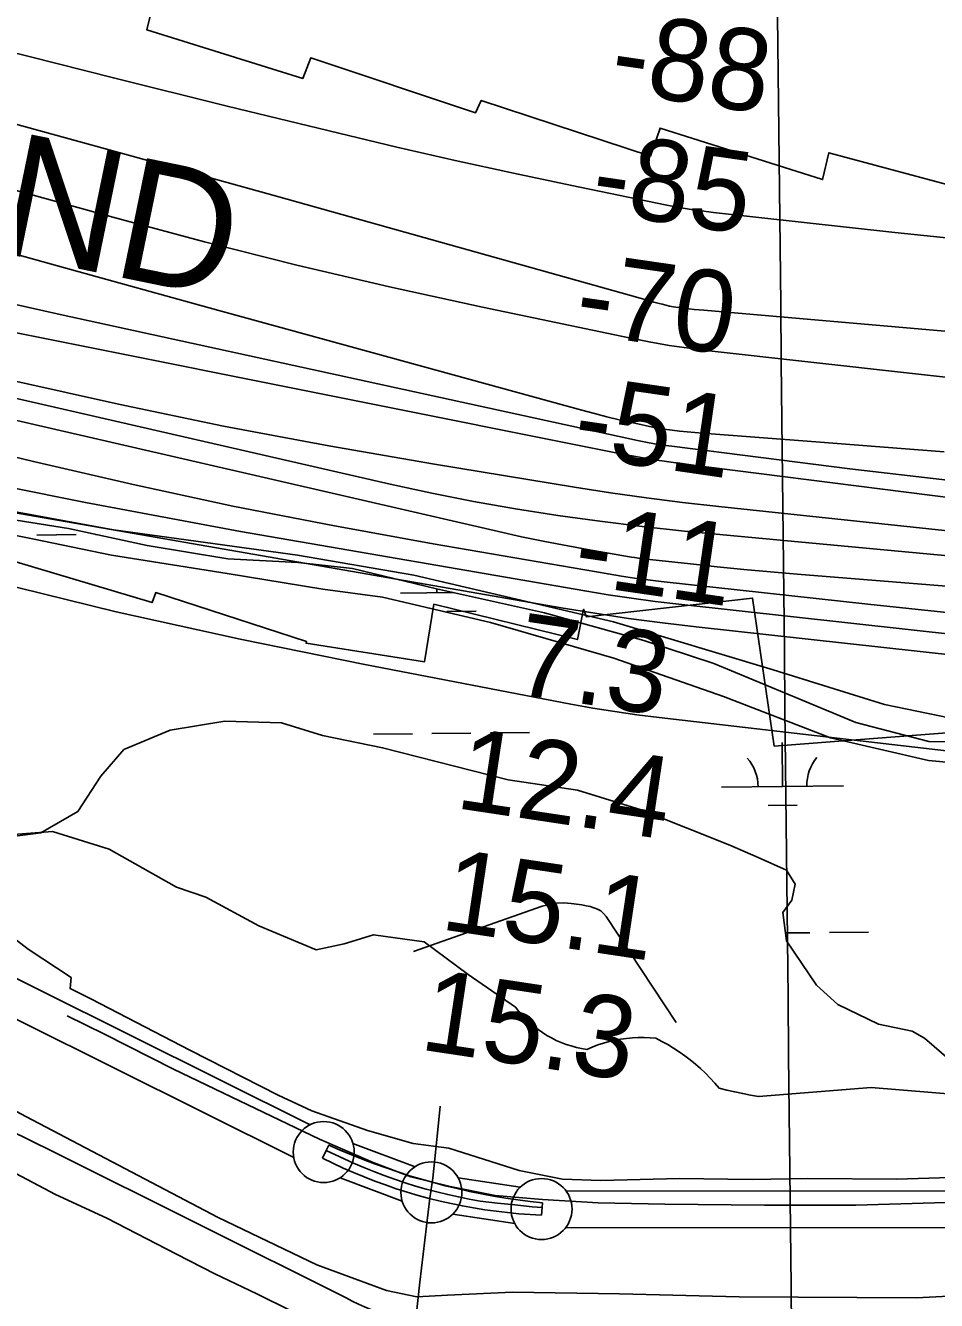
# Model space of a CAD drawing. Extents: x 3651524 to 3689615, y 505651 to 531377.
# Drawn here: x 3665685 to 3666432, y 512395 to 513440 of the extents above; entities that cross this region are included whole.
import ezdxf

# ---------------------------------------------------------------- set-up
doc = ezdxf.new("R2010")
doc.units = 0
for name, color, linetype in [('V-BRDG-OTLN', 7, 'Continuous'), ('V-FLOD-BASE', 7, 'Continuous'), ('V-GRID-MAJR', 7, 'Continuous'), ('V-LEVE-TOET', 7, 'Continuous'), ('V-RIVR-EDGE', 7, 'Continuous'), ('V-RIVR-RANG', 7, 'Continuous'), ('V-ROAD-CNTR', 7, 'Continuous'), ('V-RRAP-RVMT', 7, 'Continuous'), ('V-RRAP-RVMT-IDEN', 7, 'Continuous'), ('V-SITE-VEGE', 7, 'Continuous'), ('V-SURV-LINE', 7, 'Continuous'), ('V-TOPO-DPTH', 7, 'Continuous'), ('V-TOPO-MAJR', 7, 'Continuous'), ('V-TOPO-MINR', 7, 'Continuous'), ('V-TOPO-SHOR', 7, 'Continuous'), ('V-TOPO-WATR', 7, 'Continuous'), ('V-UTIL-LINE', 7, 'Continuous'), ('V-WETL-SWMP', 7, 'Continuous')]:
    doc.layers.add(name, color=color, linetype=linetype)

msp = doc.modelspace()

# ---------------------------------------------------------------- linework, layer by layer
at = {"layer": 'V-BRDG-OTLN'}
msp.add_lwpolyline([(3665928.931, 512511.559), (3665931.945, 512517.758), (3665934.19, 512522.374), (3665943.404, 512518.278), (3665952.698, 512514.344), (3665962.071, 512510.578), (3665971.521, 512506.977), (3665981.038, 512503.547), (3665990.623, 512500.286), (3666000.267, 512497.198), (3666009.964, 512494.286), (3666019.719, 512491.546), (3666029.518, 512488.984), (3666039.361, 512486.6), (3666049.24, 512484.394), (3666059.153, 512482.366), (3666069.096, 512480.519), (3666079.061, 512478.856), (3666089.047, 512477.375), (3666099.05, 512476.079), (3666109.06, 512474.963), (3666108.792, 512471.131), (3666108.354, 512464.924), (3666099.048, 512465.409), (3666089.748, 512466.093), (3666080.458, 512466.974), (3666071.185, 512468.057), (3666061.936, 512469.335), (3666052.714, 512470.81), (3666043.52, 512472.483), (3666034.362, 512474.346), (3666025.244, 512476.411), (3666016.171, 512478.668), (3666007.148, 512481.115), (3665998.18, 512483.755), (3665989.271, 512486.581), (3665980.424, 512489.6), (3665971.644, 512492.801), (3665962.94, 512496.19), (3665954.31, 512499.762), (3665945.763, 512503.514), (3665937.301, 512507.45)], close=True, dxfattribs=at)
msp.add_lwpolyline([(3665931.954, 512517.754), (3665954.408, 512507.614), (3665962.688, 512504.018), (3665971.052, 512500.596), (3665979.49, 512497.354), (3665988.001, 512494.292), (3665996.58, 512491.412), (3666005.221, 512488.715), (3666013.919, 512486.206), (3666022.67, 512483.884), (3666031.468, 512481.748), (3666040.305, 512479.802), (3666049.183, 512478.047), (3666058.092, 512476.483), (3666072.317, 512474.789), (3666086.555, 512473.238), (3666100.797, 512471.836), (3666108.79, 512471.131), (3666108.8, 512471.131)], dxfattribs=at)
at = {"layer": 'V-FLOD-BASE'}
msp.add_lwpolyline([(3665719.484, 512628.143), (3665750.173, 512613.311), (3665806.868, 512584.408), (3665860.874, 512558.609), (3665926.487, 512527.076), (3665970.442, 512507.909), (3666001.225, 512496.254), (3666033.549, 512488.39), (3666070.325, 512480.99), (3666109.083, 512477.611), (3666154.743, 512474.93), (3666209.525, 512473.851), (3666291.246, 512473.122), (3666366.064, 512473.028), (3666467.362, 512476.175)], dxfattribs=at)
at = {"layer": 'V-GRID-MAJR'}
msp.add_spline([(3666325.988, 511176.12), (3666261.669, 517233.653), (3666197.317, 523294.271), (3666167.785, 526075.609)], degree=3, dxfattribs=at)
at = {"layer": 'V-LEVE-TOET'}
for points in [[(3664386.871, 513072.496), (3664533.157, 513026.422), (3664686.155, 512973.7), (3664856.979, 512918.834), (3665006.421, 512864.314), (3665127.78, 512816.344), (3665265.743, 512759.809), (3665352.875, 512716.488), (3665511.962, 512638.232), (3665685.632, 512545.793), (3665843.402, 512463.078), (3665924.19, 512424.269), (3665981.294, 512403.16)], [(3665655, 512707.747), (3665687.625, 512682.962), (3665722.918, 512659.525), (3665721.943, 512650.585), (3665738.905, 512642.205), (3665820.602, 512599.836), (3665892.472, 512563.209), (3665920.143, 512550.426), (3665965.643, 512534.162), (3666003.101, 512523.65), (3666032.512, 512519.779), (3666090.047, 512501.345), (3666125.707, 512494.388), (3666156.885, 512493.198), (3666221.453, 512494.837), (3666281.129, 512494.226), (3666326.552, 512494.886), (3666399.59, 512494.337), (3666452.131, 512495.92)], [(3666031.187, 512399.388), (3666084.618, 512401.864), (3666172.356, 512400.496), (3666270.34, 512397.837), (3666415.523, 512397.184), (3666543.751, 512403.576), (3666666.147, 512418.846), (3666821.365, 512443.266), (3667033.2, 512474.279), (3667149.361, 512489.965), (3667298.004, 512510.703), (3667461.341, 512532.846), (3667565.5, 512543.133), (3667683.467, 512553.483), (3667780.077, 512559.281), (3667909.216, 512561.225), (3668049.549, 512569.097), (3668206.739, 512572.063), (3668323.846, 512575.731), (3668386.645, 512574.244)], [(3665981.294, 512403.16), (3666006.31, 512397.831), (3666031.187, 512399.388)]]:
    msp.add_lwpolyline(points, dxfattribs=at)
at = {"layer": 'V-RIVR-EDGE'}
for points in [[(3665653.21, 513045.458), (3665757.62, 513026.589), (3665908.251, 513005.806), (3666003.662, 512989.361), (3666167.457, 512951.135)], [(3666167.457, 512951.135), (3666298.231, 512911.791), (3666389.41, 512883.35), (3666495.614, 512861.476)]]:
    msp.add_lwpolyline(points, dxfattribs=at)
at = {"layer": 'V-ROAD-CNTR'}
msp.add_lwpolyline([(3665948.388, 512397.067), (3665707.347, 512517.244), (3665299.022, 512718.05), (3665160.48, 512783.825)], dxfattribs=at)
msp.add_arc((3666010.459, 512503.109), 122.873, 239.657964, 280.958256, dxfattribs=at)
at = {"layer": 'V-RRAP-RVMT'}
for points in [[(3665552.051, 513515.327), (3665787.533, 513447.498), (3665784.783, 513436.238), (3665912.777, 513396.32), (3665919.29, 513413.291), (3666054.22, 513368.153), (3666059.008, 513378.347), (3666197.78, 513332.763), (3666205.502, 513355.639), (3666338.703, 513313.466), (3666343.765, 513335.427), (3666494.756, 513294.918), (3666467.097, 513184.942)], [(3666444.06, 512860.437), (3666299.16, 512849.288), (3666281.401, 512970.49), (3666145.148, 512955.265), (3666142.901, 512961.337), (3666137.757, 512936.548), (3666020.107, 512965.537), (3666012.396, 512918.245), (3665915.454, 512933.466), (3665915.731, 512935.025), (3665792.246, 512975.019), (3665789.176, 512966.909), (3665658.82, 513005.756)]]:
    msp.add_lwpolyline(points, dxfattribs=at)
at = {"layer": 'V-SITE-VEGE'}
for points in [[(3665638.08, 513029.705), (3665691.092, 513019.182), (3665755.836, 513005.753), (3665850.705, 512990.694), (3665929.174, 512977.774), (3665977.933, 512971.357), (3666066.63, 512950.511), (3666167.768, 512921.304), (3666257.401, 512889.83), (3666345.273, 512856.133), (3666425.54, 512837.461), (3666520.383, 512828.603)], [(3666182.807, 512610.209), (3666177.988, 512609.766), (3666173.194, 512609.109), (3666168.434, 512608.234), (3666163.722, 512607.149), (3666159.06, 512605.851), (3666154.465, 512604.343), (3666149.941, 512602.631), (3666145.499, 512600.716), (3666141.198, 512601.437), (3666136.94, 512602.369), (3666132.729, 512603.506), (3666128.582, 512604.847), (3666124.504, 512606.391), (3666120.509, 512608.132), (3666116.605, 512610.067), (3666112.798, 512612.193), (3666109.101, 512614.501), (3666105.522, 512616.988), (3666102.069, 512619.646), (3666098.751, 512622.47), (3666095.576, 512625.454), (3666092.552, 512628.59), (3666089.684, 512631.868), (3666086.981, 512635.284), (3666048.317, 512662.126), (3666012.307, 512688.979), (3665970.64, 512694.541), (3665946.752, 512687.343), (3665923.739, 512682.362), (3665876.69, 512702.076), (3665833.168, 512725.349), (3665809.209, 512733.654), (3665754.13, 512764.847), (3665707.548, 512779.247), (3665672.124, 512776.422)], [(3666507.739, 512558.851), (3666378.665, 512569.39), (3666286.196, 512562.111), (3666279.737, 512563.254), (3666273.271, 512564.506), (3666266.814, 512565.865), (3666260.371, 512567.332), (3666253.959, 512568.901), (3666250.368, 512573.128), (3666246.631, 512577.222), (3666242.746, 512581.176), (3666238.717, 512584.992), (3666234.56, 512588.658), (3666230.269, 512592.168), (3666225.856, 512595.525), (3666221.322, 512598.719), (3666216.677, 512601.748), (3666211.925, 512604.603), (3666207.074, 512607.29), (3666202.128, 512609.797), (3666197.311, 512610.227), (3666192.478, 512610.438), (3666187.638, 512610.434), (3666182.807, 512610.209)]]:
    msp.add_lwpolyline(points, dxfattribs=at)
at = {"layer": 'V-SURV-LINE'}
for points in [[(3665548.874, 512723.09), (3665918.674, 512538.911)], [(3665905.284, 512512.066), (3665535.485, 512696.244)], [(3665953.834, 512523.622), (3666004.709, 512504.572)], [(3665994.183, 512476.479), (3665943.308, 512495.529)], [(3666040.143, 512495.366), (3666090.859, 512487.696)], [(3666128.364, 512484.861), (3666481.904, 512484.605)], [(3666086.389, 512458.031), (3666035.673, 512465.701)], [(3666481.881, 512454.605), (3666128.342, 512454.861)]]:
    msp.add_lwpolyline(points, dxfattribs=at)
for centre in [(3665929.866, 512516.58), (3666018.151, 512483.522), (3666108.381, 512469.875)]:
    msp.add_circle(centre, 25, dxfattribs=at)
at = {"layer": 'V-TOPO-DPTH'}
for points in [[(3667391.536, 512903.862), (3666317.776, 512990.235), (3666295.963, 512992.087), (3666274.163, 512994.068), (3666252.381, 512996.242), (3666230.611, 512998.545), (3666192.049, 513002.797), (3666189.573, 513003.093), (3666184.634, 513003.787), (3666182.172, 513004.185), (3666148.982, 513009.855), (3666129.96, 513013.273), (3666110.982, 513016.908), (3666092.069, 513020.867), (3666073.199, 513025.044), (3665189.502, 513228.594)], [(3667391.536, 512903.862), (3666317.776, 512990.235), (3666295.963, 512992.087), (3666274.163, 512994.068), (3666252.381, 512996.242), (3666230.611, 512998.545), (3666192.049, 513002.797), (3666189.573, 513003.093), (3666184.634, 513003.787), (3666182.172, 513004.185), (3666148.982, 513009.855), (3666129.96, 513013.273), (3666110.982, 513016.908), (3666092.069, 513020.867), (3666073.199, 513025.044), (3665189.502, 513228.594)], [(3665481.498, 513227.334), (3666172.066, 513089.108), (3666185.551, 513086.559), (3666199.068, 513084.204), (3666212.632, 513082.14), (3666226.228, 513080.27), (3666528.081, 513042.05), (3666673.055, 513025.131), (3666818.207, 513010.104), (3666963.624, 512997.914), (3667109.218, 512987.615), (3667364.484, 512972.063), (3667382.584, 512971.144), (3667400.69, 512970.47), (3667418.806, 512970.164), (3667436.928, 512970.102), (3668037.032, 513010.232)], [(3668037.032, 513010.232), (3667436.928, 512970.102), (3667418.806, 512970.164), (3667400.69, 512970.47), (3667382.584, 512971.144), (3667364.484, 512972.063), (3667109.218, 512987.615), (3666963.624, 512997.914), (3666818.207, 513010.104), (3666673.055, 513025.131), (3666528.081, 513042.05), (3666226.228, 513080.27), (3666212.632, 513082.14), (3666199.068, 513084.204), (3666185.551, 513086.559), (3666172.066, 513089.108), (3665481.498, 513227.334)], [(3665646.625, 513217.855), (3665713.891, 513202.808), (3666186.956, 513099.786), (3666193.953, 513098.36), (3666200.971, 513097.058), (3666208.021, 513095.944), (3666215.093, 513094.954), (3666361.067, 513076.507), (3666441.205, 513067.034), (3666521.43, 513058.425), (3666601.782, 513051.109), (3666682.22, 513044.656), (3667389.565, 512993.646), (3667396.212, 512993.231), (3667402.862, 512992.902), (3667409.517, 512992.702), (3667416.176, 512992.589), (3667500.959, 512991.961), (3668372.374, 513076.685)], [(3665646.625, 513217.855), (3665713.891, 513202.808), (3666186.956, 513099.786), (3666193.953, 513098.36), (3666200.971, 513097.058), (3666208.021, 513095.944), (3666215.093, 513094.954), (3666361.067, 513076.507), (3666441.205, 513067.034), (3666521.43, 513058.425), (3666601.782, 513051.109), (3666682.22, 513044.656), (3667389.565, 512993.646), (3667396.212, 512993.231), (3667402.862, 512992.902), (3667409.517, 512992.702), (3667416.176, 512992.589), (3667500.959, 512991.961), (3668372.374, 513076.685)], [(3665675.866, 513148.474), (3665761.676, 513129.389), (3665847.715, 513111.454), (3665934.096, 513095.245), (3666020.704, 513080.187), (3666135.32, 513061.439), (3666164.825, 513056.87), (3666194.375, 513052.634), (3666223.993, 513048.901), (3666253.656, 513045.501), (3666978.14, 512968.695), (3667047.934, 512961.906), (3667117.79, 512955.924), (3667187.74, 512951.151), (3667257.751, 512947.185), (3667332.158, 512943.616), (3667365.016, 512942.391), (3667397.881, 512941.632), (3667430.753, 512941.574), (3667463.632, 512941.982), (3668254.401, 512998.298)], [(3668254.401, 512998.298), (3667463.632, 512941.982), (3667430.753, 512941.574), (3667397.881, 512941.632), (3667365.016, 512942.391), (3667332.158, 512943.616), (3667257.751, 512947.185), (3667187.74, 512951.151), (3667117.79, 512955.924), (3667047.934, 512961.906), (3666978.14, 512968.695), (3666253.656, 513045.501), (3666223.993, 513048.901), (3666194.375, 513052.634), (3666164.825, 513056.87), (3666135.32, 513061.439), (3666020.704, 513080.187), (3665934.096, 513095.245), (3665847.715, 513111.454), (3665761.676, 513129.389), (3665675.866, 513148.474)], [(3665607.874, 513074.192), (3665734.618, 513048.733), (3665861.776, 513025.217), (3666143.78, 512976.419), (3666162.978, 512973.28), (3666182.209, 512970.378), (3666201.492, 512967.833), (3666220.807, 512965.526), (3666594.425, 512924.402), (3666726.607, 512910.788), (3666858.895, 512898.408), (3666991.343, 512887.878), (3667123.898, 512878.583), (3667344.4, 512864.669), (3667366.791, 512863.435), (3667389.19, 512862.438), (3667411.603, 512861.798), (3667434.024, 512861.396), (3667682.822, 512858.915), (3668650.487, 512965.093)], [(3665607.874, 513074.192), (3665734.618, 513048.733), (3665861.776, 513025.217), (3666143.78, 512976.419), (3666162.978, 512973.28), (3666182.209, 512970.378), (3666201.492, 512967.833), (3666220.807, 512965.526), (3666594.425, 512924.402), (3666726.607, 512910.788), (3666858.895, 512898.408), (3666991.343, 512887.878), (3667123.898, 512878.583), (3667344.4, 512864.669), (3667366.791, 512863.435), (3667389.19, 512862.438), (3667411.603, 512861.798), (3667434.024, 512861.396), (3667682.822, 512858.915), (3668650.487, 512965.093)], [(3667893.258, 512787.238), (3667407.508, 512779.298), (3667393.268, 512779.183), (3667379.029, 512779.223), (3667364.792, 512779.499), (3667350.558, 512779.93), (3667106.41, 512789.342), (3666970.223, 512796.16), (3666834.197, 512805.06), (3666698.411, 512817.084), (3666562.785, 512831.19), (3666204.752, 512872.591), (3666186.591, 512874.897), (3666168.472, 512877.474), (3666150.414, 512880.455), (3666132.399, 512883.706), (3665963.62, 512916.118), (3665861.519, 512936.955), (3665759.784, 512959.36), (3665658.594, 512984.118)]]:
    msp.add_lwpolyline(points, dxfattribs=at)
at = {"layer": 'V-TOPO-MAJR'}
msp.add_lwpolyline([(3665607.332, 513271.839), (3665721.626, 513239.983), (3665835.989, 513208.374), (3666141.526, 513124.459), (3666151.681, 513121.751), (3666161.862, 513119.143), (3666172.08, 513116.687), (3666182.323, 513114.332), (3666201.753, 513110.015), (3666202.301, 513109.902), (3666203.957, 513109.633), (3666215.332, 513108.198), (3666221.579, 513107.455), (3666227.833, 513106.773), (3666234.096, 513106.182), (3666240.365, 513105.651), (3666333.121, 513098.468), (3666385.774, 513094.416), (3666438.431, 513090.398)], dxfattribs=at)
at = {"layer": 'V-TOPO-MINR'}
for points in [[(3665664.417, 513420.335), (3665757.531, 513396.827), (3665850.753, 513373.745), (3665942.166, 513351.446), (3665989.824, 513340.098), (3666037.56, 513329.102), (3666085.414, 513318.632), (3666133.347, 513308.513), (3666209.609, 513292.853), (3666219.492, 513290.965), (3666229.404, 513289.259), (3666239.359, 513287.827), (3666249.343, 513286.577), (3666397.917, 513270.055), (3666482.272, 513261.458)], [(3665652.298, 513365.695), (3665772.804, 513332.692), (3665893.197, 513299.277), (3666196.173, 513214.347), (3666200.511, 513213.125), (3666204.845, 513211.891), (3666207.137, 513211.259), (3666211.265, 513210.237), (3666213.342, 513209.777), (3666216.62, 513209.089), (3666218.408, 513208.8), (3666225.494, 513207.991), (3666229.489, 513207.551), (3666233.486, 513207.132), (3666237.486, 513206.746), (3666241.489, 513206.381), (3667417.669, 513103.95)], [(3665666.103, 513307.914), (3665756.896, 513282.734), (3665832.269, 513262.602), (3665907.877, 513243.432), (3665983.836, 513225.706), (3666060.029, 513208.942), (3666180.18, 513183.704), (3666196.512, 513180.518), (3666212.895, 513177.647), (3666229.353, 513175.249), (3666245.862, 513173.165), (3666493.416, 513145.53)], [(3665176.543, 513249.189), (3665984.363, 513063.762), (3666018.493, 513056.381), (3666052.73, 513049.581), (3666087.129, 513043.65), (3666121.635, 513038.299), (3666156.251, 513033.634), (3666190.907, 513029.304), (3666225.622, 513025.476), (3666260.376, 513021.982), (3667205.292, 512933.885), (3667237.049, 512931.176), (3667268.828, 512928.798), (3667300.64, 512926.919), (3667332.474, 512925.373), (3667364.327, 512924.424), (3667396.182, 512923.941), (3667428.04, 512924.156), (3667459.899, 512924.836), (3668244.331, 512975.87)], [(3665189.502, 513228.594), (3666073.199, 513025.044), (3666092.069, 513020.867), (3666110.982, 513016.908), (3666129.96, 513013.273), (3666148.982, 513009.855), (3666182.172, 513004.185), (3666184.634, 513003.787), (3666189.573, 513003.093), (3666192.049, 513002.797), (3666230.611, 512998.545), (3666252.381, 512996.242), (3666274.163, 512994.068), (3666295.963, 512992.087), (3666317.776, 512990.235), (3667391.536, 512903.862)], [(3665481.498, 513227.334), (3666172.066, 513089.108), (3666185.551, 513086.559), (3666199.068, 513084.204), (3666212.632, 513082.14), (3666226.228, 513080.27), (3666528.081, 513042.05), (3666673.055, 513025.131), (3666818.207, 513010.104), (3666963.624, 512997.914), (3667109.218, 512987.615), (3667364.484, 512972.063), (3667382.584, 512971.144), (3667400.69, 512970.47), (3667418.806, 512970.164), (3667436.928, 512970.102), (3668037.032, 513010.232)], [(3665646.625, 513217.855), (3665713.891, 513202.808), (3666186.956, 513099.786), (3666193.953, 513098.36), (3666200.971, 513097.058), (3666208.021, 513095.944), (3666215.093, 513094.954), (3666361.067, 513076.507), (3666441.205, 513067.034), (3666521.43, 513058.425), (3666601.782, 513051.109), (3666682.22, 513044.656), (3667389.565, 512993.646), (3667396.212, 512993.231), (3667402.862, 512992.902), (3667409.517, 512992.702), (3667416.176, 512992.589), (3667500.959, 512991.961), (3668372.374, 513076.685)], [(3665206.955, 513199.569), (3665692.133, 513082.518), (3665773.632, 513063.714), (3665855.355, 513045.998), (3665937.415, 513029.915), (3666019.7, 513014.92), (3666162.973, 512990.284), (3666173.804, 512988.523), (3666184.654, 512986.893), (3666195.532, 512985.461), (3666206.428, 512984.16), (3666375.785, 512965.5), (3666471.424, 512955.513)], [(3665675.866, 513148.474), (3665761.676, 513129.389), (3665847.715, 513111.454), (3665934.096, 513095.245), (3666020.704, 513080.187), (3666135.32, 513061.439), (3666164.825, 513056.87), (3666194.375, 513052.634), (3666223.993, 513048.901), (3666253.656, 513045.501), (3666978.14, 512968.695), (3667047.934, 512961.906), (3667117.79, 512955.924), (3667187.74, 512951.151), (3667257.751, 512947.185), (3667332.158, 512943.616), (3667365.016, 512942.391), (3667397.881, 512941.632), (3667430.753, 512941.574), (3667463.632, 512941.982), (3668254.401, 512998.298)], [(3665502.779, 513070.846), (3666124.593, 512962.587), (3666152.155, 512958.056), (3666179.766, 512953.872), (3666207.452, 512950.21), (3666235.187, 512946.896), (3667031.402, 512859.348), (3667090.317, 512853.366), (3667149.285, 512848.041), (3667208.333, 512843.699), (3667267.435, 512840.014), (3667312.542, 512837.578), (3667349.139, 512835.904), (3667385.747, 512834.633), (3667422.371, 512833.966), (3667459.005, 512833.702), (3667876.017, 512834.129), (3667982.127, 512835.904)], [(3665658.594, 512984.118), (3665759.784, 512959.36), (3665861.519, 512936.955), (3665963.62, 512916.118), (3666132.399, 512883.706), (3666150.414, 512880.455), (3666168.472, 512877.474), (3666186.591, 512874.897), (3666204.752, 512872.591), (3666562.785, 512831.19), (3666698.411, 512817.084), (3666834.197, 512805.06), (3666970.223, 512796.16), (3667106.41, 512789.342), (3667350.558, 512779.93), (3667364.792, 512779.499), (3667379.029, 512779.223), (3667393.268, 512779.183), (3667407.508, 512779.298), (3667893.258, 512787.238)], [(3666003.452, 512680.864), (3666108.994, 512717.993), (3666114.841, 512719.583), (3666120.744, 512720.599), (3666126.732, 512720.755), (3666132.777, 512720.338), (3666141.542, 512719.087), (3666144.933, 512718.494), (3666148.279, 512717.687), (3666151.307, 512716.856), (3666154.264, 512715.68), (3666156.957, 512714.142), (3666159.256, 512712.06), (3666161.292, 512709.615), (3666218.66, 512622.82)]]:
    msp.add_lwpolyline(points, dxfattribs=at)
at = {"layer": 'V-TOPO-SHOR'}
msp.add_lwpolyline([(3665677.471, 512499.119), (3665709.983, 512481.809), (3665752.207, 512462.327), (3665809.168, 512432.936), (3665840.568, 512416.728), (3665875.013, 512400.537), (3665903.075, 512386.532), (3665916.97, 512378.836)], dxfattribs=at)
at = {"layer": 'V-TOPO-WATR'}
msp.add_lwpolyline([(3665607.874, 513074.192), (3665734.618, 513048.733), (3665861.776, 513025.217), (3666143.78, 512976.419), (3666162.978, 512973.28), (3666182.209, 512970.378), (3666201.492, 512967.833), (3666220.807, 512965.526), (3666594.425, 512924.402), (3666726.607, 512910.788), (3666858.895, 512898.408), (3666991.343, 512887.878), (3667123.898, 512878.583), (3667344.4, 512864.669), (3667366.791, 512863.435), (3667389.19, 512862.438), (3667411.603, 512861.798), (3667434.024, 512861.396), (3667682.822, 512858.915), (3668650.487, 512965.093)], dxfattribs=at)
at = {"layer": 'V-UTIL-LINE'}
for points in [[(3666025.334, 512554.116), (3666023.503, 512534.883), (3666019.268, 512495.334), (3666016.716, 512478.78)], [(3666016.716, 512478.78), (3666008.711, 512409.855), (3666001.647, 512344.78), (3665997.34, 512306.63)]]:
    msp.add_lwpolyline(points, dxfattribs=at)
at = {"layer": 'V-WETL-SWMP'}
for p, q in [((3665694.856, 513022.212), (3665726.854, 513022.556)), ((3665742.853, 513022.728), (3665742.964, 513022.729)), ((3665992.701, 512974.672), (3666036.063, 512975.139)), ((3666030.865, 512959.651), (3666054.863, 512959.91)), ((3665970.536, 512858.995), (3666002.535, 512859.34)), ((3666018.534, 512859.512), (3666050.532, 512859.856)), ((3666066.531, 512860.028), (3666098.529, 512860.373)), ((3666305.861, 512816.172), (3666305.473, 512852.17)), ((3666255.864, 512815.634), (3666355.858, 512816.71)), ((3666294.028, 512800.613), (3666318.026, 512800.871)), ((3666308.234, 512696.119), (3666328.308, 512696.335)), ((3666344.307, 512696.508), (3666376.305, 512696.852))]:
    msp.add_line(p, q, dxfattribs=at)
for points in [[(3665677.851, 513034.29), (3665720.581, 513027.511), (3665785.267, 513013.692), (3665851.336, 513002.753), (3665908.582, 512999.819), (3665953.357, 512994.692), (3666022.408, 512978.184), (3666110.771, 512958.481), (3666192.167, 512935.872), (3666249.735, 512916.846), (3666322.052, 512886.887), (3666366.068, 512868.536), (3666425.835, 512853.052), (3666473.136, 512852.206)], [(3666444.034, 512590.952), (3666422.261, 512609.822), (3666412.1, 512615.628), (3666384.521, 512621.434), (3666351.136, 512637.401), (3666333.718, 512653.368), (3666309.042, 512689.656), (3666306.139, 512712.88), (3666313.397, 512723.041), (3666316.3, 512736.104), (3666309.042, 512747.717), (3666285.818, 512757.877), (3666262.594, 512768.038), (3666190.018, 512797.068), (3666137.763, 512813.035), (3666081.153, 512821.744), (3665978.095, 512847.872), (3665928.744, 512858.032), (3665895.359, 512868.193), (3665848.91, 512869.644), (3665803.913, 512862.387), (3665766.173, 512846.42), (3665747.304, 512824.647), (3665728.434, 512795.617), (3665697.952, 512778.198), (3665674.727, 512775.295)]]:
    msp.add_lwpolyline(points, dxfattribs=at)
for centre, start, end in [((3665987.453, 512975.091), 359.844864, 4.977097), ((3666250.616, 512816.052), 359.844864, 41.388523), ((3666361.095, 512817.241), 139.844861, 181.38852)]:
    msp.add_arc(centre, 35.246, start, end, dxfattribs=at)

# ---------------------------------------------------------------- texts
at = {"layer": 'V-RIVR-RANG'}
for s, rotation, p in [('-88', 351.723667, (3666163.008, 513385.999)), ('-85', 351.723667, (3666147.324, 513287.228)), ('-70', 351.723667, (3666133.99, 513188.115)), ('-51', 351.723667, (3666132.403, 513087.294)), ('-11', 351.723667, (3666132.881, 512982.417)), ('7.3', 351.438326, (3666084.227, 512892.628)), ('12.4', 351.438326, (3666036.722, 512798.654)), ('15.1', 351.438326, (3666024.429, 512699.377)), ('15.3', 351.438326, (3666007.443, 512600.808))]:
    msp.add_text(s, height=67, rotation=rotation, dxfattribs=at).set_placement(p)
at = {"layer": 'V-RRAP-RVMT-IDEN'}
msp.add_text('BEND', height=99.9998, rotation=348.389681, dxfattribs=at).set_placement((3665484.824, 513290.578))

doc.saveas('drawing.dxf')
